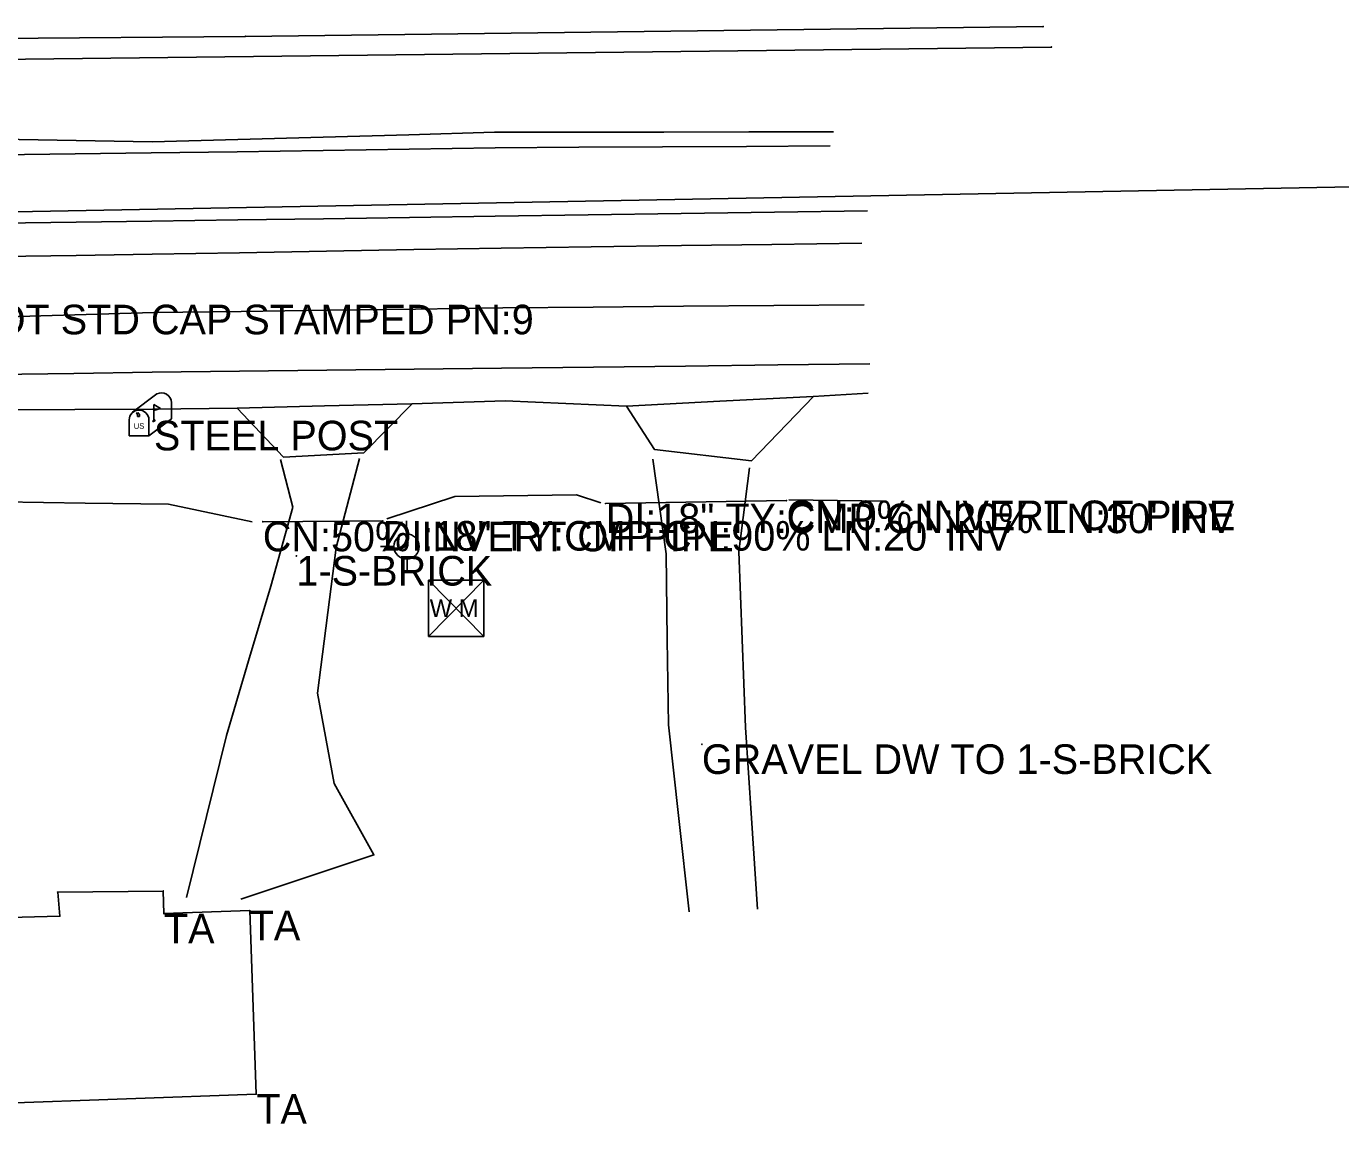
# Model space of a CAD drawing. Extents: x 1800653 to 1804042, y 522635 to 523313.
# Drawn here: x 1803136 to 1803358, y 522860.4 to 523045.6 of the extents above; entities that cross this region are included whole.
import ezdxf

# ---------------------------------------------------------------- set-up
doc = ezdxf.new("R2010")
doc.units = 0
for name, color, linetype in [('S_BASELINE', 7, 'Continuous'), ('S_BUILDING', 7, 'Continuous'), ('S_BUILDING_ANNOT', 7, 'Continuous'), ('S_DITCHLINE', 7, 'Continuous'), ('S_DRG_PT_SYM', 7, 'Continuous'), ('S_DRIVEWAY', 7, 'Continuous'), ('S_EDGE_PAVEMENT', 7, 'Continuous'), ('S_GAS_UTILITIES', 7, 'Continuous'), ('S_MAILBOX', 7, 'Continuous'), ('S_MAILBOX_ANNOT', 7, 'Continuous'), ('S_MSC_PT_SYM', 7, 'Continuous'), ('S_PAVEMENT_CROWN', 7, 'Continuous'), ('S_PRIMARY_CTL_ANNOT', 7, 'Continuous'), ('S_SHOULDER', 7, 'Continuous'), ('S_SIDE_DRAIN', 7, 'Continuous'), ('S_SIDE_DRAIN_ANNOT', 7, 'Continuous'), ('S_STR_PT_SYM', 7, 'Continuous'), ('S_SURVEY_TEXT_ANNOT', 7, 'Continuous'), ('S_UTILITY_POLE', 7, 'Continuous'), ('S_UTL_PT_SYM', 7, 'Continuous'), ('S_WATER_UTILITIES', 7, 'Continuous')]:
    doc.layers.add(name, color=color, linetype=linetype)

msp = doc.modelspace()

# ---------------------------------------------------------------- linework, layer by layer
at = {"layer": 'S_BASELINE'}
msp.add_line((1803097.96, 523013.6), (1803914.71, 523028.84), dxfattribs=at)
at = {"layer": 'S_BUILDING'}
for p, q in [((1803141.36, 522899.44), (1803159.18, 522899.62)), ((1803141.73, 522895.4), (1803141.36, 522899.44)), ((1803159.18, 522899.62), (1803159.29, 522895.81)), ((1803159.29, 522895.81), (1803173.77, 522896.33)), ((1803173.77, 522896.33), (1803174.89, 522865.35)), ((1803115.61, 522894.68), (1803141.73, 522895.4)), ((1803174.89, 522865.35), (1803116.93, 522863.25))]:
    msp.add_line(p, q, dxfattribs=at)
at = {"layer": 'S_DITCHLINE'}
for points in [[(1802954.76, 523027.19), (1802965.25, 523026.85), (1802981.47, 523027.06), (1802997.7, 523027.27), (1803010.63, 523026.85), (1803023.56, 523026.42), (1803036.49, 523025.99), (1803049.42, 523025.57), (1803063.54, 523025.91), (1803077.66, 523026.26), (1803091.77, 523026.61), (1803105.89, 523026.96), (1803118.74, 523026.75), (1803131.59, 523026.53), (1803144.45, 523026.32), (1803157.3, 523026.11), (1803171.75, 523026.51), (1803186.19, 523026.9), (1803200.64, 523027.3), (1803215.09, 523027.7), (1803229.41, 523027.72), (1803243.73, 523027.74), (1803258.05, 523027.76), (1803272.38, 523027.78)], [(1802954.86, 523026.08), (1802964.7, 523024.61), (1802981.39, 523023.77), (1802998.08, 523022.92), (1803010.85, 523022.39), (1803023.62, 523021.85), (1803036.38, 523021.31), (1803049.15, 523020.77), (1803063.29, 523021.48), (1803077.43, 523022.18), (1803091.58, 523022.88), (1803105.72, 523023.58), (1803118.57, 523023.74), (1803131.43, 523023.9), (1803144.29, 523024.05), (1803157.14, 523024.21), (1803171.66, 523024.43), (1803186.19, 523024.65), (1803200.71, 523024.88), (1803215.23, 523025.1), (1803229.37, 523025.17), (1803243.51, 523025.24), (1803257.65, 523025.32), (1803271.78, 523025.39)], [(1803049.77, 522960.68), (1803053.46, 522961.77), (1803066.04, 522962.75), (1803078.62, 522963.73), (1803091.2, 522964.71), (1803103.78, 522965.69), (1803117.85, 522965.49), (1803131.92, 522965.3), (1803146, 522965.1), (1803160.07, 522964.91), (1803174.22, 522961.96)], [(1803196.93, 522962.44), (1803208.39, 522966.23), (1803228.95, 522966.53), (1803233.06, 522965.16)], [(1803264.83, 522965.66), (1803281.26, 522965.45)]]:
    msp.add_lwpolyline(points, dxfattribs=at)
at = {"layer": 'S_DRG_PT_SYM'}
for points in [[(1803233.88, 522965.04), (1803233.88, 522965.09), (1803233.88, 522965.04), (1803233.83, 522965.04), (1803233.88, 522965.04), (1803233.88, 522964.99), (1803233.88, 522965.04), (1803233.93, 522965.04)], [(1803264.42, 522965.54), (1803264.42, 522965.59), (1803264.42, 522965.54), (1803264.37, 522965.54), (1803264.42, 522965.54), (1803264.42, 522965.49), (1803264.42, 522965.54), (1803264.47, 522965.54)], [(1803175.99, 522961.97), (1803175.99, 522962.02), (1803175.99, 522961.97), (1803175.94, 522961.97), (1803175.99, 522961.97), (1803175.99, 522961.92), (1803175.99, 522961.97), (1803176.04, 522961.97)], [(1803196.25, 522962.09), (1803196.25, 522962.14), (1803196.25, 522962.09), (1803196.2, 522962.09), (1803196.25, 522962.09), (1803196.25, 522962.04), (1803196.25, 522962.09), (1803196.3, 522962.09)]]:
    msp.add_lwpolyline(points, dxfattribs=at)
at = {"layer": 'S_DRIVEWAY'}
for points in [[(1803179, 522972.48), (1803181.07, 522964.41), (1803177.35, 522951.09), (1803173.6, 522938.49), (1803169.86, 522925.9), (1803166.47, 522912.2), (1803163.09, 522898.51)], [(1803172.26, 522898.26), (1803194.74, 522905.72), (1803188.06, 522917.78), (1803185.22, 522933.02), (1803188.4, 522957.62), (1803192.32, 522972.62)], [(1803241.84, 522972.51), (1803244.08, 522956.52), (1803244.28, 522942.09), (1803244.48, 522927.66), (1803246.24, 522911.89), (1803248, 522896.12)], [(1803259.51, 522896.59), (1803258.51, 522911.92), (1803257.52, 522927.24), (1803256.93, 522942.09), (1803256.35, 522956.94), (1803258.15, 522971.07)]]:
    msp.add_lwpolyline(points, dxfattribs=at)
at = {"layer": 'S_EDGE_PAVEMENT'}
for points in [[(1803131.69, 523006.74), (1803144.5, 523006.93), (1803157.32, 523007.11), (1803172.05, 523007.37), (1803186.77, 523007.64), (1803201.5, 523007.9), (1803216.23, 523008.16), (1803231.46, 523008.37), (1803246.7, 523008.57), (1803261.93, 523008.78), (1803277.16, 523008.99)], [(1803130.85, 522986.79), (1803144.08, 522987.01), (1803157.31, 522987.24), (1803172.05, 522987.4), (1803186.8, 522987.55), (1803201.54, 522987.71), (1803216.28, 522987.87), (1803231.84, 522988.06), (1803247.39, 522988.25), (1803262.95, 522988.45), (1803278.5, 522988.64)], [(1803237.38, 522981.45), (1803242.12, 522974.18), (1803258.5, 522972.26), (1803268.96, 522983.11)], [(1803171.66, 522981.13), (1803179.47, 522972.88), (1803193.03, 522973.57), (1803201.21, 522981.86)]]:
    msp.add_lwpolyline(points, dxfattribs=at)
at = {"layer": 'S_GAS_UTILITIES'}
msp.add_line((1803078.29, 523039.38), (1803309.15, 523042.1), dxfattribs=at)
at = {"layer": 'S_MAILBOX'}
for p, q in [((1803153.99, 522980.44), (1803158.12, 522983.55)), ((1803157.6, 522981.73), (1803157.6, 522979.01)), ((1803160.55, 522982.07), (1803160.55, 522979.36)), ((1803153.43, 522979.16), (1803153.43, 522976.45)), ((1803156.76, 522976.45), (1803160.55, 522979.36)), ((1803156.76, 522979.16), (1803156.76, 522976.45)), ((1803153.43, 522976.45), (1803156.76, 522976.45))]:
    msp.add_line(p, q, dxfattribs=at)
for points in [[(1803154.62, 522980.28), (1803154.84, 522980.14), (1803154.84, 522979.75), (1803155.14, 522979.75), (1803155.14, 522980.11), (1803154.95, 522980.36), (1803154.62, 522980.31)], [(1803157.6, 522981.73), (1803158.71, 522981.06), (1803157.6, 522980.72)]]:
    msp.add_lwpolyline(points, dxfattribs=at)
for centre, end in [((1803158.89, 522982.07), 117.5718), ((1803155.09, 522979.16), 180)]:
    msp.add_arc(centre, 1.66, 0, end, dxfattribs=at)
msp.add_ellipse((1803157.6, 522979.01), major_axis=(0.145, 0.132), ratio=0.564646, dxfattribs=at)
at = {"layer": 'S_MSC_PT_SYM'}
for points in [[(1803181.66, 522956.19), (1803181.66, 522956.24), (1803181.66, 522956.19), (1803181.61, 522956.19), (1803181.66, 522956.19), (1803181.66, 522956.14), (1803181.66, 522956.19), (1803181.71, 522956.19)], [(1803250.13, 522924.39), (1803250.13, 522924.44), (1803250.13, 522924.39), (1803250.08, 522924.39), (1803250.13, 522924.39), (1803250.13, 522924.34), (1803250.13, 522924.39), (1803250.18, 522924.39)]]:
    msp.add_lwpolyline(points, dxfattribs=at)
at = {"layer": 'S_PAVEMENT_CROWN'}
msp.add_lwpolyline([(1803130.84, 522996.49), (1803144.23, 522996.88), (1803157.61, 522997.27), (1803172.33, 522997.46), (1803187.06, 522997.66), (1803201.78, 522997.85), (1803216.5, 522998.05), (1803231.76, 522998.19), (1803247.03, 522998.33), (1803262.29, 522998.47), (1803277.55, 522998.6)], dxfattribs=at)
at = {"layer": 'S_SHOULDER'}
for points in [[(1803131.66, 523012.34), (1803144.46, 523012.52), (1803157.26, 523012.69), (1803171.75, 523012.9), (1803186.25, 523013.12), (1803200.75, 523013.33), (1803215.25, 523013.54), (1803230.95, 523013.77), (1803246.66, 523014), (1803262.37, 523014.22), (1803278.08, 523014.45)], [(1803131.05, 522980.86), (1803144.24, 522980.9), (1803157.44, 522980.95), (1803171.64, 522981.14), (1803186.39, 522981.51), (1803201.14, 522981.88), (1803216.92, 522982.39), (1803237.4, 522981.46), (1803253.18, 522982.29), (1803268.95, 522983.11), (1803278.23, 522983.67)]]:
    msp.add_lwpolyline(points, dxfattribs=at)
at = {"layer": 'S_SIDE_DRAIN'}
for p, q in [((1803233.88, 522965.04), (1803264.42, 522965.54)), ((1803196.25, 522962.09), (1803175.99, 522961.97))]:
    msp.add_line(p, q, dxfattribs=at)
at = {"layer": 'S_STR_PT_SYM'}
for points in [[(1803141.36, 522899.44), (1803141.36, 522899.49), (1803141.36, 522899.44), (1803141.31, 522899.44), (1803141.36, 522899.44), (1803141.36, 522899.39), (1803141.36, 522899.44), (1803141.41, 522899.44)], [(1803159.18, 522899.62), (1803159.18, 522899.67), (1803159.18, 522899.62), (1803159.13, 522899.62), (1803159.18, 522899.62), (1803159.18, 522899.57), (1803159.18, 522899.62), (1803159.23, 522899.62)], [(1803173.77, 522896.33), (1803173.77, 522896.38), (1803173.77, 522896.33), (1803173.72, 522896.33), (1803173.77, 522896.33), (1803173.77, 522896.28), (1803173.77, 522896.33), (1803173.82, 522896.33)], [(1803141.73, 522895.4), (1803141.73, 522895.45), (1803141.73, 522895.4), (1803141.68, 522895.4), (1803141.73, 522895.4), (1803141.73, 522895.35), (1803141.73, 522895.4), (1803141.78, 522895.4)], [(1803159.29, 522895.81), (1803159.29, 522895.86), (1803159.29, 522895.81), (1803159.24, 522895.81), (1803159.29, 522895.81), (1803159.29, 522895.76), (1803159.29, 522895.81), (1803159.34, 522895.81)], [(1803174.89, 522865.35), (1803174.89, 522865.4), (1803174.89, 522865.35), (1803174.84, 522865.35), (1803174.89, 522865.35), (1803174.89, 522865.3), (1803174.89, 522865.35), (1803174.94, 522865.35)]]:
    msp.add_lwpolyline(points, dxfattribs=at)
at = {"layer": 'S_UTILITY_POLE'}
for p, q in [((1803200.27, 522959.89), (1803200.27, 522962.14)), ((1803198.18, 522957.76), (1803195.85, 522957.76)), ((1803200.35, 522953.34), (1803200.35, 522955.67))]:
    msp.add_line(p, q, dxfattribs=at)
msp.add_circle((1803200.27, 522957.78), 2.13, dxfattribs=at)
at = {"layer": 'S_UTL_PT_SYM'}
for points in [[(1803307.76, 523045.54), (1803307.76, 523045.59), (1803307.76, 523045.54), (1803307.71, 523045.54), (1803307.76, 523045.54), (1803307.76, 523045.49), (1803307.76, 523045.54), (1803307.81, 523045.54)], [(1803173.03, 523043.9), (1803173.03, 523043.95), (1803173.03, 523043.9), (1803172.98, 523043.9), (1803173.03, 523043.9), (1803173.03, 523043.85), (1803173.03, 523043.9), (1803173.08, 523043.9)], [(1803309.15, 523042.1), (1803309.15, 523042.15), (1803309.15, 523042.1), (1803309.1, 523042.1), (1803309.15, 523042.1), (1803309.15, 523042.05), (1803309.15, 523042.1), (1803309.2, 523042.1)]]:
    msp.add_lwpolyline(points, dxfattribs=at)
at = {"layer": 'S_WATER_UTILITIES'}
for p, q in [((1803173.03, 523043.9), (1803307.76, 523045.54)), ((1803078.38, 523043.05), (1803173.03, 523043.9)), ((1803203.97, 522952.11), (1803213.31, 522952.11)), ((1803203.97, 522952.11), (1803203.97, 522942.61)), ((1803203.97, 522952.11), (1803213.31, 522942.61)), ((1803213.31, 522952.11), (1803203.97, 522942.61)), ((1803213.31, 522952.11), (1803213.31, 522942.61)), ((1803203.97, 522942.61), (1803213.31, 522942.61))]:
    msp.add_line(p, q, dxfattribs=at)

# ---------------------------------------------------------------- texts
at = {"layer": 'S_BUILDING_ANNOT'}
for p in [(1803173.77, 522891.33), (1803159.29, 522890.81), (1803174.89, 522860.35)]:
    msp.add_text('TA', height=5, dxfattribs=at).set_placement(p)
at = {"layer": 'S_MAILBOX'}
msp.add_text('US', height=0.96, dxfattribs=at).set_placement((1803154.2, 522977.64))
at = {"layer": 'S_MAILBOX_ANNOT'}
msp.add_text('STEEL POST', height=5, dxfattribs=at).set_placement((1803157.6, 522974.01))
at = {"layer": 'S_PRIMARY_CTL_ANNOT'}
msp.add_text('PD:ARDOT STD CAP STAMPED PN:9', height=5, dxfattribs=at).set_placement((1803105.46, 522993.6))
at = {"layer": 'S_SIDE_DRAIN_ANNOT'}
for s, p in [('DI:18" TY:CMP CN:20% LN:30\' INV', (1803233.88, 522960.04)), ('CN:0% INVERT OF PIPE', (1803264.42, 522960.54)), ('CN:50% INVERT OF PIPE', (1803175.99, 522956.97)), ('DI:18" TY:CMP CN:90% LN:20\' INV', (1803196.25, 522957.09))]:
    msp.add_text(s, height=5, dxfattribs=at).set_placement(p)
at = {"layer": 'S_SURVEY_TEXT_ANNOT'}
for s, p in [('1-S-BRICK', (1803181.66, 522951.19)), ('GRAVEL DW TO 1-S-BRICK', (1803250.13, 522919.39))]:
    msp.add_text(s, height=5, dxfattribs=at).set_placement(p)
at = {"layer": 'S_WATER_UTILITIES'}
msp.add_text('W M', height=3, dxfattribs=at).set_placement((1803204.17, 522945.87))

doc.saveas('drawing.dxf')
